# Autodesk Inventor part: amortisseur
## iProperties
Shininess: 64.0
Length Units: 11269
Angle Units: 11279
Time Units: 11290
Mass Units: 11283
Length Display Precision: 3
Angle Display Precision: 2
Compacted: True
Part Number: amortisseur
Document SubType Name: Modeling
Created: 2004-05
Material: Par défaut
Designer: David
Density: 0.0
Volumn: 0.0
Area: 0.0
PropertySet Name: Model Information
Control State: 0
Master: False
Checked Out: False
Author: David
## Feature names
1. Révolution1 [Revolution]
